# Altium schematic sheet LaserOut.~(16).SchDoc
size A; DocumentNumber: 5; SheetNumber: 5; SheetTotal: 6
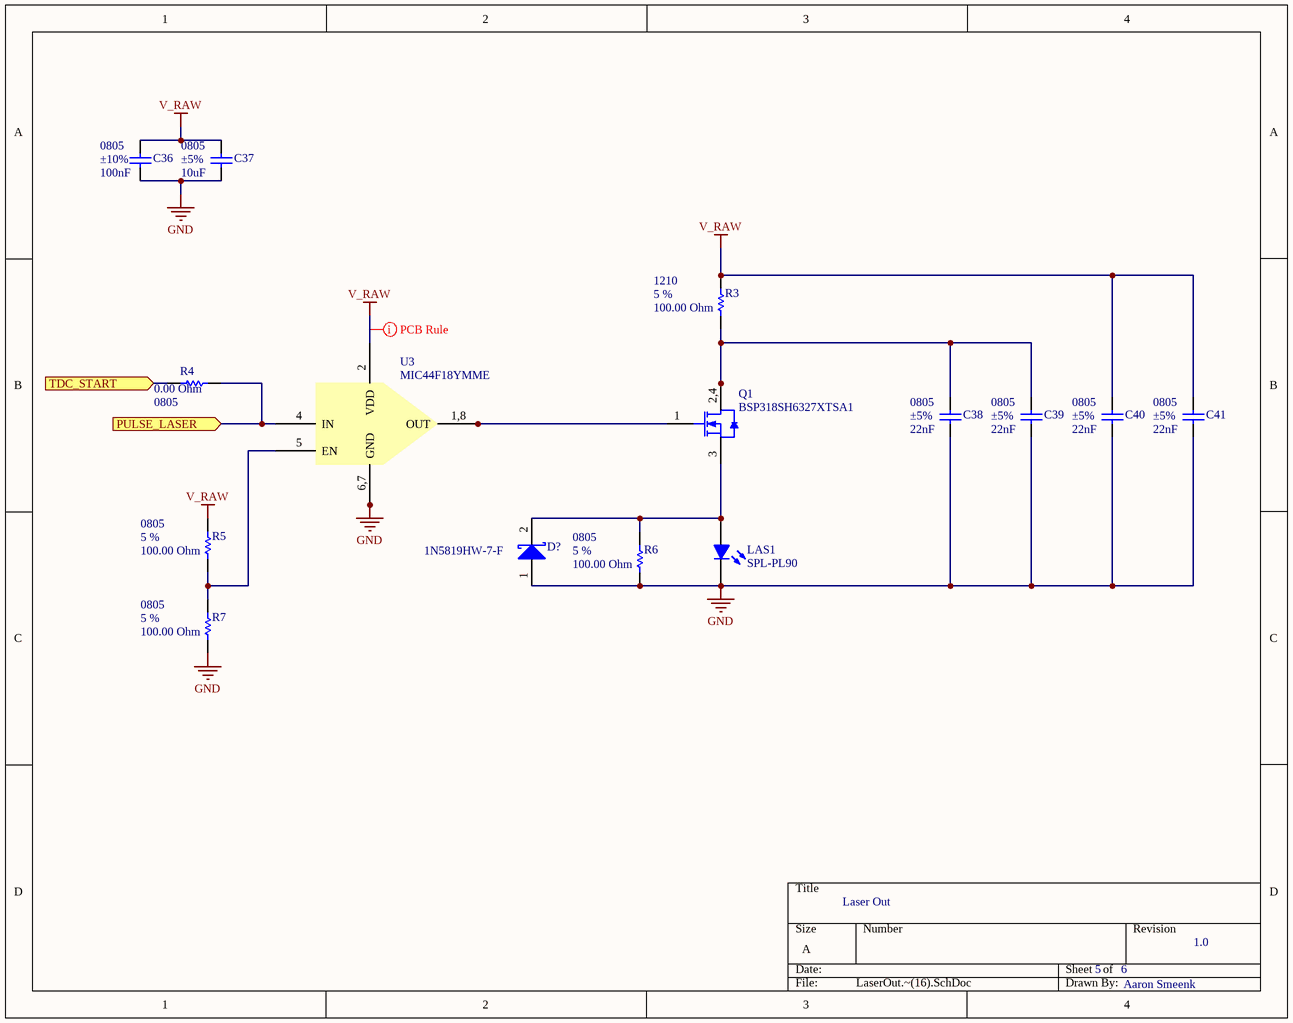
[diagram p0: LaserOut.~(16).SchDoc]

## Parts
C36  value 100nF  Case-EIA: 0805  Tolerance: ±10%  [CAPC0805(2012)100_N]  (hidden comment: CAP 100nF 6.3V 0805(2012))
C37  value 10uF  Case-EIA: 0805  Tolerance: ±5%  [CAPC0805(2012)145_N]  (hidden comment: CAP 10uF 6.3V 0805(2012))
C38  value 22nF  Case-EIA: 0805  Tolerance: ±5%  [CAPC0805(2012)100_L]  (hidden comment: CAP 22nF 6.3V 0805(2012))
C39  value 22nF  Case-EIA: 0805  Tolerance: ±5%  [CAPC0805(2012)100_L]  (hidden comment: CAP 22nF 6.3V 0805(2012))
C40  value 22nF  Case-EIA: 0805  Tolerance: ±5%  [CAPC0805(2012)100_L]  (hidden comment: CAP 22nF 6.3V 0805(2012))
C41  value 22nF  Case-EIA: 0805  Tolerance: ±5%  [CAPC0805(2012)100_L]  (hidden comment: CAP 22nF 6.3V 0805(2012))
D?  1N5819HW-7-F  [DIOD-SOD-123-2_V]
LAS1  SPL-PL90
Q1  BSP318SH6327XTSA1  [BSP318SH6327XTSA1--SOT230P700X180-4N]
R3  value 100.00 Ohm  Tolerance: 5 %  Case-EIA: 1210  [RESC1210(3225)_L]  (hidden comment: 100R 5% 1210(3225))
R4  value 0.00 Ohm  Case-EIA: 0805  [RESC0805(2012)_N]  (hidden comment: Jumper 0805(2012))
R5  value 100.00 Ohm  Case-EIA: 0805  Tolerance: 5 %  [RESC0805(2012)_M]  (hidden comment: 100R 5% 0805(2012))
R6  value 100.00 Ohm  Case-EIA: 0805  Tolerance: 5 %  [RESC0805(2012)_M]  (hidden comment: 100R 5% 0805(2012))
R7  value 100.00 Ohm  Case-EIA: 0805  Tolerance: 5 %  [RESC0805(2012)_M]  (hidden comment: 100R 5% 0805(2012))
U3  MIC44F18YMME  [MIC44F18YMME--TSOP65P490X108_HS-9N]

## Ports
PULSE_LASER (in), TDC_START (in)

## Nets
GND: C36.1 C37.1 C38.1 C39.1 C40.1 C41.1 D?.1(A) LAS1.2(K) R6.1 R7.1 U3.6(GND) U3.7(GND)
V_RAW: C36.2 C37.2 C40.2 C41.2 R3.2 R5.2 U3.2(VDD)
PULSE_LASER: R4.2 U3.4(IN) ; port PULSE_LASER
TDC_START: R4.1 ; port TDC_START
NetC38_2: C38.2 C39.2 Q1.2(D) Q1.4(D) R3.1
NetD?_2: D?.2(K) LAS1.1(A) Q1.3(S) R6.2
NetQ1_1: Q1.1(G) U3.1(OUT) U3.8(OUT)
NetR5_1: R5.1 R7.2 U3.5(EN)

Not connected (* = marked no-connect by the designer): U3 3(NC)

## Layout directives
rule Supply Nets [Voltage = 7.400]: V_RAW

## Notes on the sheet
- Laser Out
- 5
- 6
- 1.0
- Aaron Smeenk

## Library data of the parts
C36 = CMP-1036-04391-1: CAP 100nF 6.3V ±10% 0805 (2012 Metric) Thickness 1mm SMD; Case-Metric: 2012
C37 = CMP-1036-04781-1: CAP 10uF 6.3V ±5% 0805 (2012 Metric) Thickness 1.45mm SMD; Case-Metric: 2012
C38-C41 = CMP-1036-04030-1: CAP 22nF 6.3V ±5% 0805 (2012 Metric) Thickness 1mm SMD; Case-Metric: 2012
D? = CMP-0303-00003-1: 1.0 A Surface Mount Schottky Barrier Rectifier, 40 V, -65 to 125 degC, 2-Pin SOD-123 Package, RoHS, Tape and Reel; Manufacturer: Diodes Inc; @ VR (V): 40; @ Terminal Temperature TT (degC): 90; Maximum Average Rectified Current IO (A): 1; Total Capacitance CT (pF): 50; Peak Forward Surge Current IFSM (A): 25; Forward Voltage Drop VF (V): 0.45; VR (RMS) (V): 28
Q1 = BSP318SH6327XTSA1: MOSFET N-Ch 60V 2.6A SOT-223-3
R3 = CMP-1015-00050-1: 100R 0.5W 5% 1210 (3225 Metric)  SMD; Case-Metric: 3225
R4 = CMP-1013-00001-1: Jumper 0805 (2012 Metric); Tolerance: None; Case-Metric: 2012
R5-R7 = CMP-1013-00050-1: 100R 0.125W 5% 0805 (2012 Metric)  SMD; Case-Metric: 2012
U3 = MIC44F18YMME: Gate Drivers 3A High Speed MOSFET Driver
